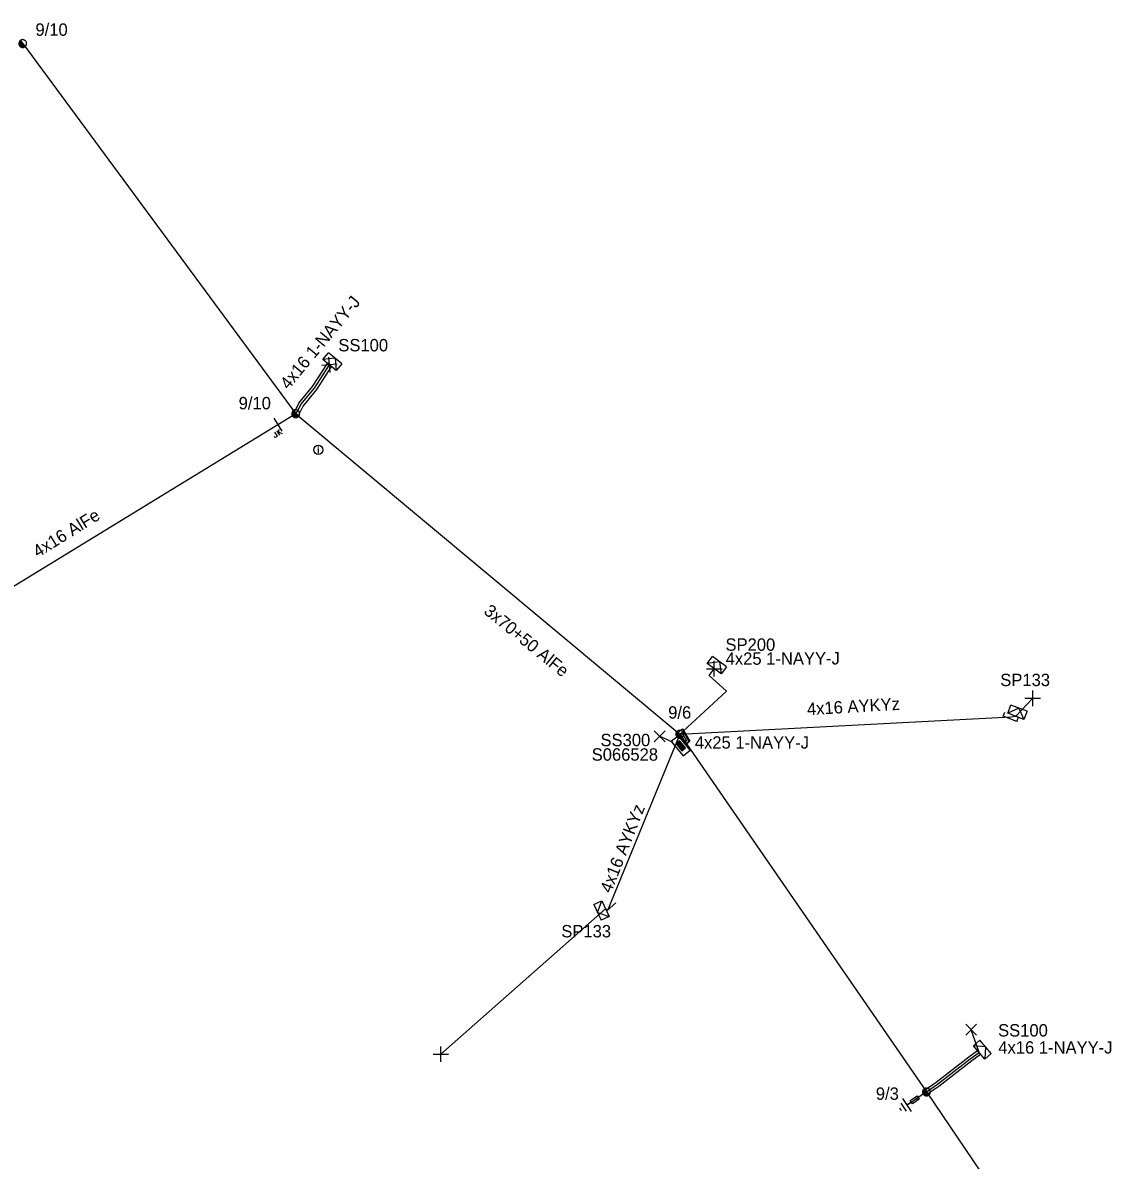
# Model space of a CAD drawing. Extents: x -717562 to -713845, y -1151196 to -1143903.
# Drawn here: x -717081 to -716993.1, y -1144446.2 to -1144354.4 of the extents above; entities that cross this region are included whole.
import ezdxf

# ---------------------------------------------------------------- set-up
doc = ezdxf.new("R2010")
doc.units = 0
for name, color, linetype in [('Vrstva 1', 7, 'Continuous'), ('Vrstva 10', 7, 'Continuous'), ('Vrstva 12', 7, 'Continuous'), ('Vrstva 13', 7, 'Continuous'), ('Vrstva 14', 7, 'Continuous'), ('Vrstva 15', 7, 'Continuous'), ('Vrstva 16', 7, 'Continuous'), ('Vrstva 18', 7, 'Continuous'), ('Vrstva 2', 7, 'Continuous'), ('Vrstva 20', 7, 'Continuous'), ('Vrstva 28', 7, 'Continuous'), ('Vrstva 29', 7, 'Continuous'), ('Vrstva 30', 7, 'Continuous'), ('Vrstva 31', 7, 'Continuous'), ('Vrstva 33', 7, 'Continuous'), ('Vrstva 34', 7, 'Continuous'), ('Vrstva 36', 7, 'Continuous'), ('Vrstva 4', 7, 'Continuous'), ('Vrstva 5', 7, 'Continuous'), ('Vrstva 52', 7, 'Continuous'), ('Vrstva 53', 7, 'Continuous'), ('Vrstva 54', 7, 'Continuous'), ('Vrstva 55', 7, 'Continuous'), ('Vrstva 59', 7, 'Continuous'), ('Vrstva 6', 7, 'Continuous'), ('Vrstva 8', 7, 'Continuous'), ('Vrstva 9', 7, 'Continuous')]:
    doc.layers.add(name, color=color, linetype=linetype)

# ---------------------------------------------------------------- blocks, each defined once
blk = doc.blocks.new('NN440')
at = {"layer": 'Vrstva 2'}
for points in [[(0.63, 0), (0.63, 0.06), (0.62, 0.13), (0.6, 0.19), (0.58, 0.25), (0.55, 0.31), (0.51, 0.37), (0.47, 0.42), (0.42, 0.46), (0.37, 0.51), (0.32, 0.54), (0.26, 0.57), (0.2, 0.59), (0.13, 0.61), (0.07, 0.62), (0, 0.63), (-0.06, 0.62), (-0.13, 0.61), (-0.19, 0.59), (-0.26, 0.57), (-0.31, 0.54), (-0.37, 0.51), (-0.42, 0.46), (-0.47, 0.42), (-0.51, 0.37), (-0.54, 0.31), (-0.57, 0.25), (-0.6, 0.19), (-0.62, 0.13), (-0.63, 0.06), (-0.63, 0), (-0.63, -0.07), (-0.62, -0.14), (-0.6, -0.2), (-0.57, -0.26), (-0.54, -0.32), (-0.51, -0.37), (-0.47, -0.43), (-0.42, -0.47), (-0.37, -0.51), (-0.31, -0.55), (-0.26, -0.58), (-0.19, -0.6), (-0.13, -0.62), (-0.06, -0.63), (0, -0.63), (0.07, -0.63), (0.13, -0.62), (0.2, -0.6), (0.26, -0.58), (0.32, -0.55), (0.37, -0.51), (0.42, -0.47), (0.47, -0.43), (0.51, -0.37), (0.55, -0.32), (0.58, -0.26), (0.6, -0.2), (0.62, -0.14), (0.63, -0.07), (0.63, 0)], [(-0.63, 0), (0.63, 0)], [(-0.6, -0.18), (0.57, -0.18)], [(-0.51, -0.32), (0.5, -0.32)], [(-0.37, -0.47), (0.35, -0.47)]]:
    blk.add_lwpolyline(points, dxfattribs=at)
blk = doc.blocks.new('NN840')
at = {"layer": 'Vrstva 15'}
for points in [[(0.003, 0.619), (0.003, -0.631)], [(-0.745, -0.71), (-0.745, -0.66)], [(-0.73, -0.764), (-0.745, -0.71)], [(-0.657, -0.798), (-0.73, -0.764)], [(-0.627, -0.798), (-0.657, -0.798)], [(-0.558, -0.764), (-0.627, -0.798)], [(-0.538, -0.71), (-0.558, -0.764)], [(-0.538, -0.385), (-0.538, -0.71)], [(-0.332, -0.385), (-0.332, -0.798)], [(-0.332, -0.641), (-0.125, -0.385)], [(-0.263, -0.557), (-0.091, -0.798)]]:
    blk.add_lwpolyline(points, dxfattribs=at)
blk = doc.blocks.new('NN770')
at = {"layer": 'Vrstva 10'}
for p, q in [((0.002, 0.187), (0.002, 0.263)), ((0.002, -0.276), (0.002, 0.111))]:
    blk.add_line(p, q, dxfattribs=at)
blk.add_circle((0, -0.008), 0.375, dxfattribs=at)
blk = doc.blocks.new('NN800')
at = {"layer": 'Vrstva 1'}
for points in [[(-0.442, 0.442), (0.442, -0.442)], [(-0.442, -0.442), (0.442, 0.442)]]:
    blk.add_lwpolyline(points, dxfattribs=at)
blk = doc.blocks.new('NN820')
at = {"layer": 'Vrstva 13'}
for points in [[(-0.003, 0.004), (-0.003, -1.049)], [(-0.165, -0.813), (0.165, -0.813)], [(-0.165, -1.473), (-0.165, -0.813)], [(0.165, -0.813), (0.165, -1.473)], [(0.165, -1.473), (-0.165, -1.473)], [(-0.003, -1.049), (-0.062, -0.926)], [(-0.003, -1.049), (0.057, -0.926)], [(-0.003, -1.473), (-0.003, -1.871)]]:
    blk.add_lwpolyline(points, dxfattribs=at)
blk = doc.blocks.new('NN620')
at = {"layer": 'Vrstva 8'}
for points in [[(0.752, 0.004), (-0.748, 0.004)], [(-0.748, 0.004), (-0.748, -0.746)], [(0.752, -0.746), (0.752, 0.004)], [(-0.748, -0.746), (0.752, -0.746)], [(0.368, -0.18), (-0.376, -0.18)], [(-0.376, -0.18), (-0.376, -0.558)], [(-0.376, -0.558), (0.368, -0.558)], [(0.321, -0.227), (-0.329, -0.227)], [(-0.329, -0.227), (-0.329, -0.51)], [(-0.329, -0.51), (0.321, -0.51)], [(0.274, -0.274), (-0.281, -0.274)], [(-0.281, -0.274), (-0.281, -0.463)], [(-0.281, -0.463), (0.274, -0.463)], [(0.227, -0.321), (-0.234, -0.321)], [(-0.234, -0.321), (-0.234, -0.416)], [(-0.234, -0.416), (0.227, -0.416)], [(-0.193, -0.369), (0.185, -0.369)], [(0.227, -0.416), (0.227, -0.321)], [(0.274, -0.463), (0.274, -0.274)], [(0.321, -0.51), (0.321, -0.227)], [(0.368, -0.558), (0.368, -0.18)]]:
    blk.add_lwpolyline(points, dxfattribs=at)
blk = doc.blocks.new('NN630')
at = {"layer": 'Vrstva 9'}
for points in [[(-0.003, -0.7), (-0.703, 0)], [(-0.703, -0.7), (-0.703, 0), (0.697, 0), (0.697, -0.7)], [(-0.703, -0.7), (0.697, -0.7)], [(-0.003, -0.7), (0.697, 0)]]:
    blk.add_lwpolyline(points, dxfattribs=at)
blk = doc.blocks.new('NN810')
at = {"layer": 'Vrstva 14'}
for points in [[(0.004, -0.64), (0.004, -1.89)], [(0.629, -1.89), (-0.621, -1.89)], [(0.388, -2.2), (-0.399, -2.2)], [(0.004, -2.515), (-0.124, -2.515)], [(0.137, -2.515), (0.004, -2.515)]]:
    blk.add_lwpolyline(points, dxfattribs=at)
blk = doc.blocks.new('NN510')
at = {"layer": 'Vrstva 2'}
blk.add_lwpolyline([(0.001, 0.002), (0.001, 0.939)], dxfattribs=at)
blk = doc.blocks.new('NN515')
at = {"layer": 'Vrstva 2'}
for points in [[(-0.59, 0.176), (0.591, 0.176)], [(-0.59, 0.176), (-0.59, -0.179)], [(0.591, 0.176), (0.591, -0.179)]]:
    blk.add_lwpolyline(points, dxfattribs=at)

msp = doc.modelspace()

# ---------------------------------------------------------------- linework, layer by layer
at = {"layer": 'Vrstva 1'}
for points in [[(-717080.996, -1144356.058), (-717058.967, -1144385.939), (-717027.97, -1144411.81)], [(-717027.97, -1144411.81), (-717008.05, -1144440.68), (-716994.278, -1144461.052)]]:
    msp.add_lwpolyline(points, dxfattribs=at)
at = {"layer": 'Vrstva 20'}
for points in [[(-717056.072, -1144382.108), (-717057.278, -1144383.988), (-717058.371, -1144385.309), (-717058.73, -1144386.048), (-717059.09, -1144385.872), (-717058.709, -1144385.091), (-717057.602, -1144383.752), (-717056.408, -1144381.892)], [(-717028.091, -1144411.651), (-717027.742, -1144411.384), (-717027.154, -1144412.38), (-717027.467, -1144412.659), (-717027.733, -1144412.361), (-717027.666, -1144412.3), (-717027.858, -1144411.975)], [(-717003.692, -1144437.661), (-717004.4, -1144438.18), (-717007.042, -1144440.232), (-717007.937, -1144440.845), (-717008.163, -1144440.515), (-717007.278, -1144439.908), (-717004.64, -1144437.86), (-717003.928, -1144437.339)]]:
    msp.add_lwpolyline(points, close=True, dxfattribs=at)
at = {"layer": 'Vrstva 4'}
msp.add_lwpolyline([(-717058.966, -1144385.939), (-717086.976, -1144403.089), (-717090.376, -1144404.589)], dxfattribs=at)
at = {"layer": 'Vrstva 5'}
msp.add_lwpolyline([(-717027.97, -1144411.81), (-717027.8, -1144411.68), (-717027.41, -1144412.34), (-717027.6, -1144412.51)], dxfattribs=at)
at = {"layer": 'Vrstva 52'}
for points in [[(-717058.966, -1144385.939), (-717058.682, -1144385.492), (-717058.54, -1144385.2), (-717057.44, -1144383.87), (-717056.24, -1144382)], [(-717027.503, -1144412.638), (-717027.225, -1144412.377), (-717027.698, -1144411.554), (-717024.19, -1144408.33), (-717025.6, -1144407.07), (-717025.181, -1144406.518)], [(-717008.05, -1144440.68), (-717007.16, -1144440.07), (-717004.52, -1144438.02), (-717003.81, -1144437.5)]]:
    msp.add_lwpolyline(points, dxfattribs=at)
at = {"layer": 'Vrstva 54'}
for points in [[(-717027.97, -1144411.81), (-717001.237, -1144410.399), (-717000.847, -1144410.358)], [(-717027.97, -1144411.81), (-717033.809, -1144426.04), (-717033.962, -1144425.897)]]:
    msp.add_lwpolyline(points, dxfattribs=at)
at = {"layer": 'Vrstva 59'}
for points in [[(-717000.847, -1144410.358), (-716999.476, -1144408.91)], [(-717028.494, -1144412.474), (-717029.596, -1144411.969)], [(-717033.962, -1144425.897), (-717047.25, -1144437.63)], [(-717003.81, -1144437.5), (-717004.445, -1144435.664)]]:
    msp.add_lwpolyline(points, dxfattribs=at)

# ---------------------------------------------------------------- block references
at = {"layer": 'Vrstva 13'}
for p, xscale, yscale, rotation in [((-717080.996, -1144356.059), 0.5, 0.5, -53.90663601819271), ((-717058.966, -1144385.939), 0.5000000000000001, 0.5000000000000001, -56.67143615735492), ((-717027.97, -1144411.81), 0.5, 0.5, -39.24250827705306), ((-717008.05, -1144440.68), 0.5000000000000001, 0.5, -58.48024443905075)]:
    msp.add_blockref('NN440', p, dxfattribs=dict(at, xscale=xscale, yscale=yscale, rotation=rotation))
for name, p, rotation in [('NN515', (-717001.236, -1144410.399), 158.9175472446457), ('NN510', (-717033.826, -1144426.039), -48.76156396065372)]:
    msp.add_blockref(name, p, dxfattribs=dict(at, rotation=rotation))
at = {"layer": 'Vrstva 15', "rotation": -55.94065263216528}
msp.add_blockref('NN810', (-717008.05, -1144440.68), dxfattribs=at)
at = {"layer": 'Vrstva 16', "rotation": -55.94065263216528}
msp.add_blockref('NN820', (-717008.05, -1144440.68), dxfattribs=at)
at = {"layer": 'Vrstva 18', "rotation": 31.480214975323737}
msp.add_blockref('NN840', (-717060.405, -1144386.82), dxfattribs=at)
at = {"layer": 'Vrstva 28', "rotation": -50.780634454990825}
msp.add_blockref('NN620', (-717027.6, -1144412.51), dxfattribs=at)
at = {"layer": 'Vrstva 31'}
for p, rotation in [((-717056.24, -1144382), 139.86451810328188), ((-717025.182, -1144406.52), 143.7875916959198), ((-717000.846, -1144410.359), 158.9175472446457), ((-717033.962, -1144425.897), -65.03945282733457), ((-717003.81, -1144437.5), 130.91438318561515)]:
    msp.add_blockref('NN630', p, dxfattribs=dict(at, rotation=rotation))
at = {"layer": 'Vrstva 34'}
for p, rotation in [((-717056.24, -1144382), 139.86451810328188), ((-717025.181, -1144406.518), 45), ((-716999.476, -1144408.911), 45), ((-717047.25, -1144437.63), 45)]:
    msp.add_blockref('NN800', p, dxfattribs=dict(at, rotation=rotation))
for p in [(-717029.596, -1144411.969), (-717004.445, -1144435.664)]:
    msp.add_blockref('NN800', p, dxfattribs=at)
at = {"layer": 'Vrstva 36'}
msp.add_blockref('NN770', (-717057.138, -1144388.845), dxfattribs=at)

# ---------------------------------------------------------------- texts
at = {"layer": 'Vrstva 12'}
for s, p in [('9/10', (-717079.971, -1144355.433)), ('9/10', (-717063.569, -1144385.585)), ('9/6', (-717028.901, -1144410.554)), ('9/3', (-717012.14, -1144441.32))]:
    msp.add_text(s, height=1, dxfattribs=at).set_placement(p)
at = {"layer": 'Vrstva 2'}
msp.add_text('3x70+50 AlFe', height=1, rotation=320.757, dxfattribs=at).set_placement((-717043.856, -1144402.012))
at = {"layer": 'Vrstva 29'}
msp.add_text('S066528', height=1, dxfattribs=at).set_placement((-717035.074, -1144413.945))
at = {"layer": 'Vrstva 30'}
msp.add_text('SS300', height=1, dxfattribs=at).set_placement((-717034.363, -1144412.776))
at = {"layer": 'Vrstva 33'}
for s, p in [('SS100', (-717055.524, -1144380.906)), ('SP200', (-717024.274, -1144405.073)), ('SP133', (-717002.095, -1144407.926)), ('SP133', (-717037.527, -1144428.209)), ('SS100', (-717002.27, -1144436.21))]:
    msp.add_text(s, height=1, dxfattribs=at).set_placement(p)
at = {"layer": 'Vrstva 53'}
msp.add_text('4x16 AlFe', height=1, rotation=31.872, dxfattribs=at).set_placement((-717079.778, -1144397.583))
at = {"layer": 'Vrstva 54'}
for s, rotation, p in [('4x16 1-NAYY-J', 50.407, (-717059.554, -1144384.055)), ('4x25 1-NAYY-J', 0.189, (-717024.26, -1144406.21))]:
    msp.add_text(s, height=1, rotation=rotation, dxfattribs=at).set_placement(p)
msp.add_text('4x16 1-NAYY-J', height=1, dxfattribs=at).set_placement((-717002.255, -1144437.592))
at = {"layer": 'Vrstva 55'}
for rotation, p in [(3.313, (-717017.67, -1144410.276)), (68.439, (-717033.513, -1144424.696))]:
    msp.add_text('4x16 AYKYz', height=1, rotation=rotation, dxfattribs=at).set_placement(p)
at = {"layer": 'Vrstva 6'}
msp.add_text('4x25 1-NAYY-J', height=1, dxfattribs=at).set_placement((-717026.751, -1144412.975))

doc.saveas('drawing.dxf')
